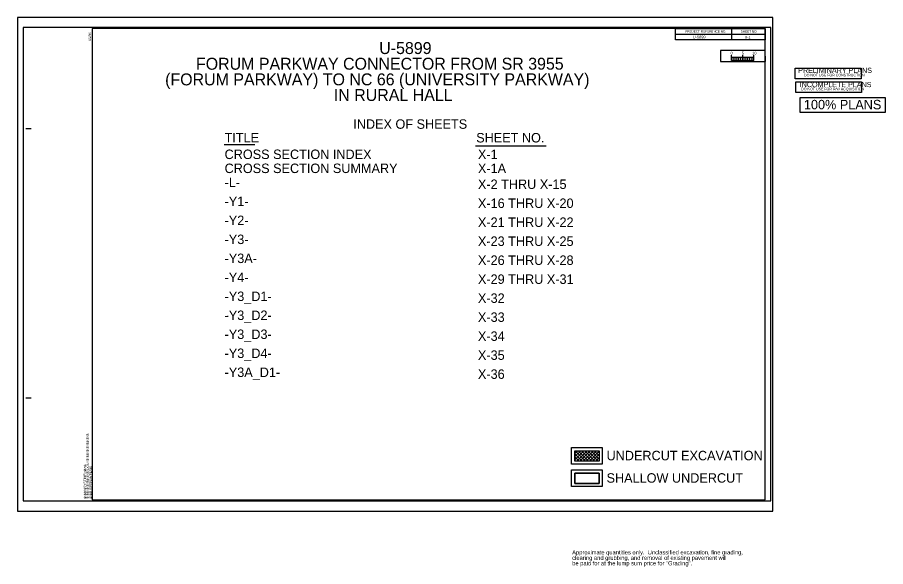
# Model space of a CAD drawing. Extents: x -19 to 368, y -25 to 220.
import ezdxf

# ---------------------------------------------------------------- set-up
doc = ezdxf.new("R2010")
doc.units = 0
for name, color, linetype in [('Default', 7, 'Continuous'), ('Old_Level_38', 7, 'Continuous'), ('Old_Level_40', 7, 'Continuous'), ('Old_Level_41', 7, 'Continuous'), ('Prop XS Sheet Number', 7, 'Continuous'), ('Prop XS Undercut Exc Hatch', 7, 'Continuous'), ('Sheet Cutting Line CELL', 7, 'Continuous'), ('Sheet Plot Border Inside CELL', 7, 'Continuous'), ('Sheet Plot Border Outside CELL', 7, 'Continuous'), ('Sheet Sticker Incomplete CELL', 7, 'Continuous'), ('Sheet Sticker Preliminary CELL', 7, 'Continuous'), ('Sheet Summary Combination CELL', 7, 'Continuous'), ('Sheet Typical CELL', 7, 'Continuous')]:
    doc.layers.add(name, color=color, linetype=linetype)

msp = doc.modelspace()

# ---------------------------------------------------------------- linework, layer by layer
at = {"layer": 'Default'}
msp.add_lwpolyline([(229.63, 12.31), (240.49, 12.31), (240.49, 16.89), (229.63, 16.89), (229.63, 12.31)], dxfattribs=at)
at = {"layer": 'Old_Level_38'}
for p, q in [((299.45, 200.79), (299.45, 203.2)), ((299.45, 202.2), (299.45, 203.2)), ((304.45, 200.79), (304.45, 203.2)), ((309.45, 200.79), (309.45, 203.2)), ((309.45, 202.2), (309.45, 203.2))]:
    msp.add_line(p, q, dxfattribs=at)
for points in [[(309.45, 202.2), (299.45, 202.2), (299.45, 200.79), (309.45, 200.79)], [(299.45, 202.2), (300.45, 202.2), (300.45, 200.79), (299.45, 200.79)], [(301.45, 202.2), (302.45, 202.2), (302.45, 200.79), (301.45, 200.79)], [(303.45, 202.2), (304.45, 202.2), (304.45, 200.79), (303.45, 200.79)], [(305.45, 202.2), (306.45, 202.2), (306.45, 200.79), (305.45, 200.79)], [(307.45, 202.2), (308.45, 202.2), (308.45, 200.79), (307.45, 200.79)]]:
    msp.add_lwpolyline(points, close=True, dxfattribs=at)
at = {"layer": 'Old_Level_40'}
msp.add_line((314.45, 202.8), (314.45, 200.3), dxfattribs=at)
msp.add_lwpolyline([(314.45, 205.3), (294.45, 205.3), (294.45, 200.3), (314.45, 200.3)], close=True, dxfattribs=at)
at = {"layer": 'Old_Level_41'}
msp.add_line((294.45, 205.3), (294.45, 200.33), dxfattribs=at)
at = {"layer": 'Prop XS Undercut Exc Hatch'}
for p, q in [((229.63, 22.91), (233.6, 26.88)), ((229.63, 24.33), (232.19, 26.88)), ((229.63, 25.74), (230.77, 26.88)), ((229.63, 25.56), (232.88, 22.31)), ((229.63, 24.14), (231.47, 22.31)), ((229.72, 26.88), (234.3, 22.31)), ((230.44, 22.31), (235.02, 26.88)), ((231.13, 26.88), (235.71, 22.31)), ((231.85, 22.31), (236.43, 26.88)), ((232.55, 26.88), (237.12, 22.31)), ((233.27, 22.31), (237.84, 26.88)), ((233.96, 26.88), (238.54, 22.31)), ((234.68, 22.31), (239.26, 26.88)), ((235.38, 26.88), (239.95, 22.31)), ((236.09, 22.31), (240.49, 26.71)), ((236.79, 26.88), (240.49, 23.18)), ((237.51, 22.31), (240.49, 25.29)), ((238.2, 26.88), (240.49, 24.59)), ((238.92, 22.31), (240.49, 23.88)), ((239.62, 26.88), (240.49, 26.01)), ((229.63, 22.73), (230.05, 22.31)), ((240.34, 22.31), (240.49, 22.46))]:
    msp.add_line(p, q, dxfattribs=at)
for points in [[(229.63, 26.88), (240.49, 26.88), (240.49, 22.31), (229.63, 22.31)], [(229.63, 16.89), (240.49, 16.89), (240.49, 12.31), (229.63, 12.31)]]:
    msp.add_lwpolyline(points, close=True, dxfattribs=at)
at = {"layer": 'Sheet Cutting Line CELL'}
for p, q in [((317.85, 220.01), (-18.95, 220.01)), ((-18.95, 220.01), (-18.95, 0.01)), ((-18.95, 0.01), (317.85, 0.01))]:
    msp.add_line(p, q, dxfattribs=at)
at = {"layer": 'Sheet Plot Border Inside CELL'}
msp.add_lwpolyline([(316.95, 215.52), (-16.35, 215.52), (-16.35, 4.5), (316.95, 4.5)], close=True, dxfattribs=at)
at = {"layer": 'Sheet Plot Border Outside CELL'}
msp.add_lwpolyline([(317.85, 220.01), (-18.95, 220.01), (-18.95, 0.01), (317.85, 0.01)], close=True, dxfattribs=at)
at = {"layer": 'Sheet Sticker Incomplete CELL'}
msp.add_lwpolyline([(328.05, 186.58), (328.05, 191.28), (357.45, 191.28), (357.45, 186.58)], close=True, dxfattribs=at)
at = {"layer": 'Sheet Sticker Preliminary CELL'}
msp.add_lwpolyline([(327.85, 192.63), (327.85, 197.33), (357.25, 197.33), (357.25, 192.63)], close=True, dxfattribs=at)
at = {"layer": 'Sheet Summary Combination CELL'}
for p, q in [((73.24, 163.43), (86.96, 163.43)), ((185.35, 162.74), (216.78, 162.74))]:
    msp.add_line(p, q, dxfattribs=at)
for points in [[(329.95, 177.82), (368.14, 177.82), (368.14, 184.11), (329.95, 184.11)], [(228.05, 28.34), (241.82, 28.34), (241.82, 20.88), (228.05, 20.88)], [(228.05, 18.35), (241.82, 18.35), (241.82, 10.89), (228.05, 10.89)]]:
    msp.add_lwpolyline(points, close=True, dxfattribs=at)
at = {"layer": 'Sheet Typical CELL'}
for p, q in [((299.45, 215), (299.45, 210)), ((274.44, 212.5), (314.45, 212.5)), ((-15.25, 170.51), (-12.75, 170.51)), ((-15.25, 50.51), (-12.75, 50.51)), ((14.45, 5.01), (14.45, 5.01)), ((14.45, 5.01), (14.45, 5.01)), ((14.45, 5.01), (14.45, 5.01)), ((14.45, 5.01), (14.45, 5.01)), ((14.45, 5.01), (14.45, 5.01)), ((14.45, 5.01), (14.45, 5.01))]:
    msp.add_line(p, q, dxfattribs=at)
for points in [[(314.45, 215.01), (14.45, 215.01), (14.45, 5.01), (314.45, 5.01)], [(274.44, 215.01), (314.45, 215.01), (314.45, 210), (274.44, 210)]]:
    msp.add_lwpolyline(points, close=True, dxfattribs=at)
msp.add_lwpolyline([(21.95, 5.01), (21.95, 5.01)], dxfattribs=at)

# ---------------------------------------------------------------- texts
at = {"layer": 'Old_Level_38'}
for s, p in [('0', (298.99, 203.42)), ('5', (304.01, 203.42)), ('10', (308.64, 203.42))]:
    msp.add_text(s, height=1.25, dxfattribs=at).set_placement(p)
at = {"layer": 'Old_Level_40'}
for s, height, p in [('U-5899', 1.25, (282.21, 210.63)), ('Approximate quantities only.  Unclassified excavation, fine grading, ', 1.86, (228.4, -19.32)), ('clearing and grubbing, and removal of existing pavement will ', 1.86, (228.4, -21.76)), ('be paid for at the lump sum price for "Grading".', 1.86, (228.4, -24.19))]:
    msp.add_text(s, height=height, dxfattribs=at).set_placement(p)
at = {"layer": 'Prop XS Sheet Number'}
msp.add_text('X-1', height=1.25, dxfattribs=at).set_placement((305.26, 210.5))
at = {"layer": 'Sheet Sticker Incomplete CELL'}
for s, height, p in [('INCOMPLETE PLANS', 2.304, (329.84, 188.92)), ('DO NOT USE FOR R/W ACQUISITION', 1.152, (330.49, 187.53))]:
    msp.add_text(s, height=height, dxfattribs=at).set_placement(p)
at = {"layer": 'Sheet Sticker Preliminary CELL'}
for s, height, p in [('PRELIMINARY PLANS', 2.304, (329.15, 195.26)), ('DO NOT USE FOR CONSTRUCTION', 1.152, (331.77, 193.72))]:
    msp.add_text(s, height=height, dxfattribs=at).set_placement(p)
at = {"layer": 'Sheet Summary Combination CELL'}
for s, height, p in [('U-5899', 5.316, (142.37, 203.67)), ('FORUM PARKWAY CONNECTOR FROM SR 3955', 5.3161, (60.68, 196.68)), ('(FORUM PARKWAY) TO NC 66 (UNIVERSITY PARKWAY)', 5.3161, (46.92, 189.71)), ('IN RURAL HALL', 5.3161, (122.13, 182.75)), ('INDEX OF SHEETS', 4.2188, (130.81, 170.36)), ('TITLE', 4.219, (73.43, 164.27)), ('SHEET NO.', 4.219, (185.61, 164.27)), ('CROSS SECTION INDEX', 4.2188, (73.43, 156.88)), ('X-1', 4.219, (186.38, 156.88)), ('CROSS SECTION SUMMARY', 4.2188, (73.43, 150.63)), ('X-1A', 4.219, (186.38, 150.63)), ('-L-', 4.219, (73.43, 144.37)), ('X-2 THRU X-15', 4.2188, (186.38, 143.54)), ('-Y1-', 4.219, (73.43, 135.91)), ('X-16 THRU X-20', 4.2188, (186.38, 135.08)), ('-Y2-', 4.219, (73.43, 127.45)), ('X-21 THRU X-22', 4.2188, (186.38, 126.62)), ('-Y3-', 4.219, (73.43, 118.99)), ('X-23 THRU X-25', 4.2188, (186.38, 118.15)), ('-Y3A-', 4.219, (73.43, 110.53)), ('X-26 THRU X-28', 4.2188, (186.38, 109.69)), ('-Y4-', 4.219, (73.43, 102.06)), ('X-29 THRU X-31', 4.2188, (186.38, 101.23)), ('-Y3_D1-', 4.219, (73.43, 93.6)), ('X-32', 4.219, (186.38, 92.77)), ('-Y3_D2-', 4.219, (73.43, 85.14)), ('X-33', 4.219, (186.38, 84.31)), ('-Y3_D3-', 4.219, (73.43, 76.68)), ('X-34', 4.219, (186.38, 75.84)), ('-Y3_D4-', 4.219, (73.43, 68.21)), ('X-35', 4.219, (186.38, 67.38)), ('-Y3A_D1-', 4.219, (73.43, 59.75)), ('X-36', 4.219, (186.38, 58.92)), ('UNDERCUT EXCAVATION', 4.2188, (243.72, 22.63)), ('SHALLOW UNDERCUT', 4.2188, (243.72, 12.64))]:
    msp.add_text(s, height=height, rotation=0.0119, dxfattribs=at).set_placement(p)
msp.add_text('100% PLANS', height=4.219, dxfattribs=at).set_placement((331.71, 179.03))
at = {"layer": 'Sheet Typical CELL'}
for s, p in [('6/2/99', (13.82, 209.46)), ('$$$$$$$$$$$$$$$$DGN$$$$$$$$$$$$$$$$', (12.92, 5.49)), ('$$$$$$SYSTIME$$$$$', (11.71, 5.49)), ('$$$$USERNAME$$$$', (14.23, 5.49))]:
    msp.add_text(s, height=1.05, rotation=90, dxfattribs=at).set_placement(p)
for s, p in [('PROJECT REFERENCE NO.', (278.87, 213.25)), ('SHEET NO.', (303.51, 213.25))]:
    msp.add_text(s, height=1, dxfattribs=at).set_placement(p)

doc.saveas('drawing.dxf')
